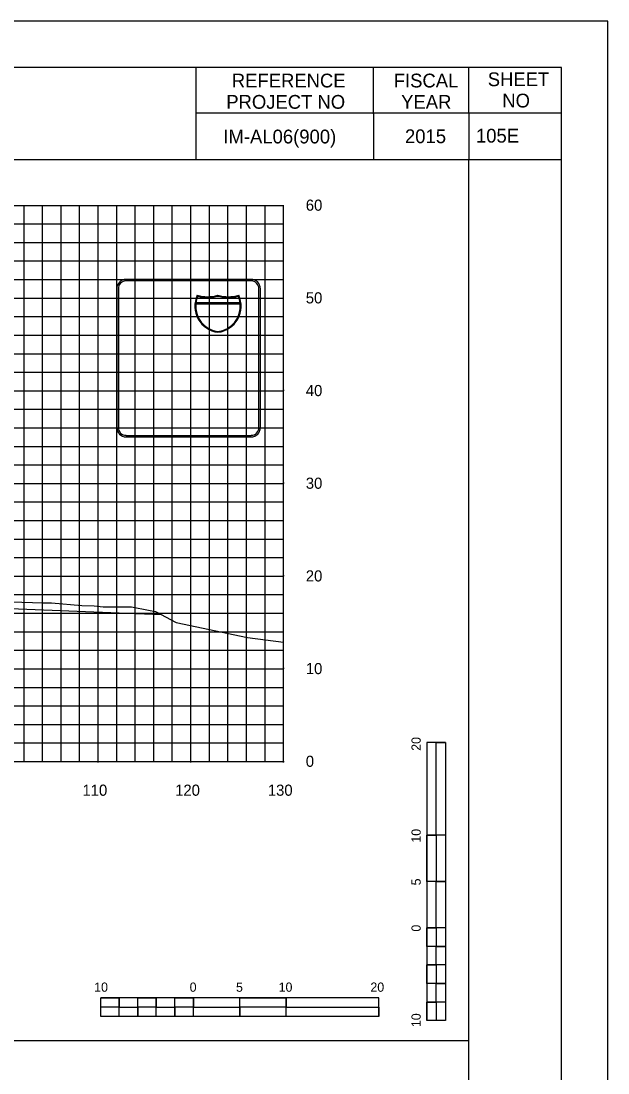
# Model space of a CAD drawing. Extents: x 2193008 to 2198143, y 1236112 to 1237864.
# Drawn here: x 2194789.4 to 2194852.7, y 1237224.5 to 1237338 of the extents above; entities that cross this region are included whole.
import ezdxf

# ---------------------------------------------------------------- set-up
doc = ezdxf.new("R2010")
doc.units = 0
for name, color, linetype in [('10', 7, 'Continuous'), ('2', 7, 'Continuous'), ('3', 7, 'Continuous'), ('31', 7, 'Continuous'), ('60', 7, 'Continuous'), ('ANNO-SHT', 7, 'Continuous'), ('CL-CNST', 7, 'Continuous'), ('GSOUTLINE', 7, 'Continuous'), ('Level 1', 7, 'Continuous'), ('Level 6', 7, 'Continuous'), ('Level 62', 7, 'Continuous'), ('M-ROADS', 7, 'Continuous'), ('SHT-BDR', 7, 'Continuous'), ('SHT-BNDRY', 7, 'Continuous')]:
    doc.layers.add(name, color=color, linetype=linetype)

msp = doc.modelspace()

# ---------------------------------------------------------------- linework, layer by layer
at = {"layer": '2'}
msp.add_lwpolyline([(2194837.65, 1237281.19), (2194837.66, 1237280.19)], dxfattribs=at)
msp.add_lwpolyline([(2194837.65, 1237281.19), (2194837.66, 1237280.19)], dxfattribs=at)
at = {"layer": '3'}
msp.add_line((2194537.69, 1237228.05), (2194837.69, 1237228.05), dxfattribs=at)
at = {"layer": '60'}
for p, q in [((2194817.69, 1237258.17), (2194817.69, 1237318.17)), ((2194817.75, 1237298.17), (2194817.69, 1237298.17)), ((2194817.75, 1237288.17), (2194817.69, 1237288.17)), ((2194817.75, 1237278.17), (2194817.69, 1237278.17)), ((2194817.75, 1237268.17), (2194817.69, 1237268.17)), ((2194817.69, 1237258.11), (2194557.69, 1237258.11)), ((2194797.69, 1237258.05), (2194797.69, 1237258.11)), ((2194807.69, 1237258.05), (2194807.69, 1237258.11)), ((2194817.69, 1237258.05), (2194817.69, 1237258.11)), ((2194817.75, 1237258.11), (2194817.69, 1237258.11))]:
    msp.add_line(p, q, dxfattribs=at)
at = {"layer": 'CL-CNST'}
msp.add_lwpolyline([(2194684.08, 1237276.52), (2194694.08, 1237276.12), (2194695.33, 1237275.85), (2194695.33, 1237275.85), (2194696.58, 1237276.12), (2194706.58, 1237276.52), (2194718.59, 1237276.78), (2194722.94, 1237276.68), (2194734.94, 1237276.42), (2194746.94, 1237276.16), (2194758.94, 1237275.89), (2194759.93, 1237275.85), (2194760.01, 1237275.78), (2194768.94, 1237275.42), (2194770.94, 1237275.34), (2194804.49, 1237274)], dxfattribs=at)
at = {"layer": 'GSOUTLINE'}
for p, q in [((2194799.7, 1237309.16), (2194799.7, 1237294.17)), ((2194799.87, 1237309.16), (2194799.87, 1237294.17)), ((2194814.19, 1237310.16), (2194800.7, 1237310.16)), ((2194814.19, 1237309.99), (2194800.7, 1237309.99)), ((2194815.03, 1237294.17), (2194815.03, 1237309.16)), ((2194815.19, 1237294.17), (2194815.19, 1237309.16)), ((2194800.7, 1237293.33), (2194814.19, 1237293.33)), ((2194800.7, 1237293.17), (2194814.19, 1237293.17))]:
    msp.add_line(p, q, dxfattribs=at)
for points in [[(2194808.21, 1237307.54), (2194813.01, 1237307.54)], [(2194813.01, 1237307.62), (2194808.22, 1237307.62)]]:
    msp.add_lwpolyline(points, dxfattribs=at)
for centre, major_axis, start_param, end_param in [((2194800.7, 1237309.16), (1, 0), 1.570796, 3.141593), ((2194800.7, 1237309.16), (0.833, 0), 1.570796, 3.141593), ((2194814.19, 1237309.16), (1, 0), 0, 1.570796), ((2194814.19, 1237309.16), (0.833, 0), 0, 1.570796), ((2194810.95, 1237307.27), (2.83, 0), 2.709569, 4.594469), ((2194810.95, 1237307.27), (2.75, 0), 2.735396, 3.01287), ((2194809.49, 1237312.29), (4, 0), 4.428637, 4.996141), ((2194809.49, 1237312.29), (4.08, 0), 4.446475, 4.990194), ((2194811.73, 1237312.29), (4, 0), 4.428637, 4.996141), ((2194810.28, 1237307.27), (2.83, 0), 4.830309, 6.715209), ((2194811.73, 1237312.29), (4.08, 0), 4.434584, 4.978303), ((2194810.28, 1237307.27), (2.75, 0), 0.128722, 0.406196), ((2194810.95, 1237307.27), (2.75, 0), 3.043371, 4.590878), ((2194810.28, 1237307.27), (2.75, 0), 4.8339, 6.381407), ((2194800.7, 1237294.17), (1, 0), 3.141593, 4.712389), ((2194800.7, 1237294.17), (0.833, 0), 3.141593, 4.712389), ((2194814.19, 1237294.17), (1, 0), 4.712389, 6.283185), ((2194814.19, 1237294.17), (0.833, 0), 4.712389, 6.283185)]:
    msp.add_ellipse(centre, major_axis=major_axis, ratio=0.999829, start_param=start_param, end_param=end_param, dxfattribs=at)
at = {"layer": 'Level 1'}
for p, q in [((2194833.16, 1237260.19), (2194833.16, 1237230.19)), ((2194835.16, 1237260.19), (2194833.16, 1237260.19)), ((2194835.16, 1237260.19), (2194835.16, 1237250.19)), ((2194835.16, 1237260.19), (2194835.16, 1237230.19)), ((2194834.16, 1237250.19), (2194833.16, 1237250.19)), ((2194835.16, 1237250.19), (2194833.16, 1237250.19)), ((2194834.16, 1237250.19), (2194834.16, 1237245.19)), ((2194835.16, 1237245.19), (2194833.16, 1237245.19)), ((2194835.16, 1237245.19), (2194834.16, 1237245.19)), ((2194835.16, 1237245.19), (2194835.16, 1237240.19)), ((2194834.16, 1237240.19), (2194833.16, 1237240.19)), ((2194835.16, 1237240.19), (2194833.16, 1237240.19)), ((2194834.16, 1237240.19), (2194834.16, 1237238.19)), ((2194835.16, 1237238.19), (2194834.16, 1237238.19)), ((2194835.16, 1237238.19), (2194835.16, 1237236.19)), ((2194834.16, 1237236.19), (2194833.16, 1237236.19)), ((2194834.16, 1237236.19), (2194834.16, 1237234.19)), ((2194835.16, 1237234.19), (2194834.16, 1237234.19)), ((2194835.16, 1237234.19), (2194835.16, 1237232.19)), ((2194827.96, 1237232.63), (2194797.96, 1237232.63)), ((2194797.96, 1237230.63), (2194797.96, 1237232.63)), ((2194799.96, 1237231.63), (2194799.96, 1237232.63)), ((2194803.96, 1237231.63), (2194803.96, 1237232.63)), ((2194807.96, 1237231.63), (2194807.96, 1237232.63)), ((2194807.96, 1237230.63), (2194807.96, 1237232.63)), ((2194812.96, 1237230.63), (2194812.96, 1237232.63)), ((2194817.96, 1237231.63), (2194817.96, 1237232.63)), ((2194817.96, 1237230.63), (2194817.96, 1237232.63)), ((2194827.96, 1237230.63), (2194827.96, 1237232.63)), ((2194834.16, 1237232.19), (2194833.16, 1237232.19)), ((2194834.16, 1237232.19), (2194834.16, 1237230.19)), ((2194799.96, 1237231.63), (2194797.96, 1237231.63)), ((2194801.96, 1237230.63), (2194801.96, 1237231.63)), ((2194803.96, 1237231.63), (2194801.96, 1237231.63)), ((2194805.96, 1237230.63), (2194805.96, 1237231.63)), ((2194807.96, 1237231.63), (2194805.96, 1237231.63)), ((2194812.96, 1237230.63), (2194812.96, 1237231.63)), ((2194817.96, 1237231.63), (2194812.96, 1237231.63)), ((2194827.96, 1237230.63), (2194797.96, 1237230.63)), ((2194801.96, 1237230.63), (2194799.96, 1237230.63)), ((2194805.96, 1237230.63), (2194803.96, 1237230.63)), ((2194812.96, 1237230.63), (2194807.96, 1237230.63)), ((2194827.96, 1237230.63), (2194817.96, 1237230.63)), ((2194835.16, 1237230.19), (2194833.16, 1237230.19))]:
    msp.add_line(p, q, dxfattribs=at)
for points in [[(2194834.16, 1237250.19), (2194834.16, 1237260.19), (2194835.16, 1237260.19), (2194835.16, 1237250.19)], [(2194833.16, 1237245.19), (2194833.16, 1237250.19), (2194834.16, 1237250.19), (2194834.16, 1237245.19)], [(2194834.16, 1237240.19), (2194834.16, 1237245.19), (2194835.16, 1237245.19), (2194835.16, 1237240.19)], [(2194833.16, 1237238.19), (2194833.16, 1237240.19), (2194834.16, 1237240.19), (2194834.16, 1237238.19)], [(2194834.16, 1237236.19), (2194834.16, 1237238.19), (2194835.16, 1237238.19), (2194835.16, 1237236.19)], [(2194833.16, 1237234.19), (2194833.16, 1237236.19), (2194834.16, 1237236.19), (2194834.16, 1237234.19)], [(2194834.16, 1237232.19), (2194834.16, 1237234.19), (2194835.16, 1237234.19), (2194835.16, 1237232.19)], [(2194797.96, 1237232.63), (2194799.96, 1237232.63), (2194799.96, 1237231.63), (2194797.96, 1237231.63)], [(2194801.96, 1237232.63), (2194803.96, 1237232.63), (2194803.96, 1237231.63), (2194801.96, 1237231.63)], [(2194805.96, 1237232.63), (2194807.96, 1237232.63), (2194807.96, 1237231.63), (2194805.96, 1237231.63)], [(2194812.96, 1237232.63), (2194817.96, 1237232.63), (2194817.96, 1237231.63), (2194812.96, 1237231.63)], [(2194833.16, 1237230.19), (2194833.16, 1237232.19), (2194834.16, 1237232.19), (2194834.16, 1237230.19)], [(2194799.96, 1237231.63), (2194801.96, 1237231.63), (2194801.96, 1237230.63), (2194799.96, 1237230.63)], [(2194803.96, 1237231.63), (2194805.96, 1237231.63), (2194805.96, 1237230.63), (2194803.96, 1237230.63)], [(2194807.96, 1237231.63), (2194812.96, 1237231.63), (2194812.96, 1237230.63), (2194807.96, 1237230.63)], [(2194817.96, 1237231.63), (2194827.96, 1237231.63), (2194827.96, 1237230.63), (2194817.96, 1237230.63)]]:
    msp.add_lwpolyline(points, close=True, dxfattribs=at)
at = {"layer": 'Level 6'}
for p, q in [((2194808.23, 1237333.04), (2194808.23, 1237323.05)), ((2194827.4, 1237328.04), (2194827.4, 1237333.04)), ((2194837.69, 1237328.17), (2194837.69, 1237333.04)), ((2194847.69, 1237328.1), (2194808.23, 1237328.1)), ((2194827.4, 1237328.04), (2194827.4, 1237323.05)), ((2194837.69, 1237328.17), (2194837.69, 1237323.05)), ((2194847.69, 1237323.05), (2194809.44, 1237323.05))]:
    msp.add_line(p, q, dxfattribs=at)
at = {"layer": 'Level 62'}
for p, q in [((2194817.69, 1237318.11), (2194557.69, 1237318.11)), ((2194789.69, 1237258.11), (2194789.69, 1237318.11)), ((2194791.69, 1237258.11), (2194791.69, 1237318.11)), ((2194793.69, 1237258.11), (2194793.69, 1237318.11)), ((2194795.69, 1237258.11), (2194795.69, 1237318.11)), ((2194797.69, 1237258.11), (2194797.69, 1237318.11)), ((2194799.69, 1237258.11), (2194799.69, 1237318.11)), ((2194801.69, 1237258.11), (2194801.69, 1237318.11)), ((2194803.69, 1237258.11), (2194803.69, 1237318.11)), ((2194805.69, 1237258.11), (2194805.69, 1237318.11)), ((2194807.69, 1237258.11), (2194807.69, 1237318.11)), ((2194809.69, 1237258.11), (2194809.69, 1237318.11)), ((2194811.69, 1237258.11), (2194811.69, 1237318.11)), ((2194813.69, 1237258.11), (2194813.69, 1237318.11)), ((2194815.69, 1237258.11), (2194815.69, 1237318.11)), ((2194817.69, 1237258.11), (2194817.69, 1237318.11)), ((2194817.69, 1237316.11), (2194557.69, 1237316.11)), ((2194817.69, 1237314.11), (2194557.69, 1237314.11)), ((2194817.69, 1237312.11), (2194557.69, 1237312.11)), ((2194817.69, 1237310.11), (2194557.69, 1237310.11)), ((2194817.69, 1237308.11), (2194557.69, 1237308.11)), ((2194817.69, 1237306.11), (2194557.69, 1237306.11)), ((2194817.69, 1237304.11), (2194557.69, 1237304.11)), ((2194817.69, 1237302.11), (2194557.69, 1237302.11)), ((2194817.69, 1237300.11), (2194557.69, 1237300.11)), ((2194817.69, 1237298.11), (2194557.69, 1237298.11)), ((2194817.69, 1237296.11), (2194557.69, 1237296.11)), ((2194817.69, 1237294.11), (2194557.69, 1237294.11)), ((2194817.69, 1237292.11), (2194557.69, 1237292.11)), ((2194817.69, 1237290.11), (2194557.69, 1237290.11)), ((2194817.69, 1237288.11), (2194557.69, 1237288.11)), ((2194817.69, 1237286.11), (2194557.69, 1237286.11)), ((2194817.69, 1237284.11), (2194557.69, 1237284.11)), ((2194817.69, 1237282.11), (2194557.69, 1237282.11)), ((2194817.69, 1237280.11), (2194557.69, 1237280.11)), ((2194817.69, 1237278.11), (2194557.69, 1237278.11)), ((2194817.69, 1237276.11), (2194557.69, 1237276.11)), ((2194817.69, 1237274.11), (2194557.69, 1237274.11)), ((2194817.69, 1237272.11), (2194557.69, 1237272.11)), ((2194817.69, 1237270.11), (2194557.69, 1237270.11)), ((2194817.69, 1237268.11), (2194557.69, 1237268.11)), ((2194817.69, 1237266.11), (2194557.69, 1237266.11)), ((2194817.69, 1237264.11), (2194557.69, 1237264.11)), ((2194817.69, 1237262.11), (2194557.69, 1237262.11)), ((2194817.69, 1237260.11), (2194557.69, 1237260.11)), ((2194817.69, 1237258.11), (2194557.69, 1237258.11))]:
    msp.add_line(p, q, dxfattribs=at)
msp.add_lwpolyline([(2194512.69, 1237118.04), (2194852.69, 1237118.04), (2194852.69, 1237338.04), (2194512.69, 1237338.04)], close=True, dxfattribs=at)
at = {"layer": 'M-ROADS'}
msp.add_lwpolyline([(2194784.76, 1237275.48), (2194791.77, 1237275.28), (2194792.64, 1237275.26), (2194795.94, 1237274.97), (2194797.26, 1237274.94), (2194798.24, 1237274.85), (2194799.92, 1237274.85), (2194801.3, 1237274.85), (2194803.11, 1237274.48), (2194803.89, 1237274.32), (2194806.1, 1237273.15), (2194813.8, 1237271.53), (2194817.69, 1237271.03)], dxfattribs=at)
at = {"layer": 'SHT-BDR'}
msp.add_lwpolyline([(2194537.69, 1237133.05), (2194837.69, 1237133.05), (2194837.69, 1237323.05), (2194537.69, 1237323.05)], close=True, dxfattribs=at)
at = {"layer": 'SHT-BNDRY'}
msp.add_lwpolyline([(2194525.19, 1237123.04), (2194847.69, 1237123.04), (2194847.69, 1237333.04), (2194525.19, 1237333.04)], close=True, dxfattribs=at)

# ---------------------------------------------------------------- texts
at = {"layer": '10'}
for s, p in [('110', (2194795.99, 1237254.45)), ('120', (2194805.99, 1237254.45)), ('130', (2194815.99, 1237254.45))]:
    msp.add_text(s, height=1.2, dxfattribs=at).set_placement(p)
at = {"layer": '31'}
for s, p in [('60', (2194820.09, 1237317.57)), ('50', (2194820.09, 1237307.57)), ('40', (2194820.09, 1237297.57)), ('30', (2194820.09, 1237287.57)), ('20', (2194820.09, 1237277.57)), ('10', (2194820.09, 1237267.57)), ('0', (2194820.09, 1237257.57))]:
    msp.add_text(s, height=1.2, dxfattribs=at).set_placement(p)
at = {"layer": 'ANNO-SHT'}
for s, height, p in [(' IM-AL06(900) ', 1.4899, (2194810.64, 1237324.83)), ('2015', 1.49, (2194830.79, 1237324.86)), ('  105E ', 1.49, (2194837.34, 1237324.92))]:
    msp.add_text(s, height=height, rotation=360, dxfattribs=at).set_placement(p)
at = {"layer": 'Level 1'}
for s, height, rotation, p in [('20', 0.999, 90.0572, (2194832.49, 1237259.3)), ('10', 0.999, 90.0572, (2194832.49, 1237249.39)), ('5', 1, 90.0572, (2194832.49, 1237244.78)), ('0', 1, 90.0572, (2194832.49, 1237239.79)), ('10', 0.999, 0.0572, (2194797.26, 1237233.3)), ('0', 1, 0.0572, (2194807.56, 1237233.3)), ('5', 0.999, 0.0572, (2194812.56, 1237233.3)), ('10', 0.999, 0.0572, (2194817.16, 1237233.3)), ('20', 0.999, 0.0572, (2194827.06, 1237233.3)), ('10', 0.999, 90.0572, (2194832.49, 1237229.49))]:
    msp.add_text(s, height=height, rotation=rotation, dxfattribs=at).set_placement(p)
at = {"layer": 'Level 6'}
for s, p in [('REFERENCE', (2194812.11, 1237330.87)), ('FISCAL', (2194829.58, 1237330.87)), ('SHEET', (2194839.72, 1237331.01)), ('PROJECT NO', (2194811.51, 1237328.57)), ('YEAR', (2194830.38, 1237328.57)), ('NO', (2194841.29, 1237328.71))]:
    msp.add_text(s, height=1.488, dxfattribs=at).set_placement(p)

doc.saveas('drawing.dxf')
